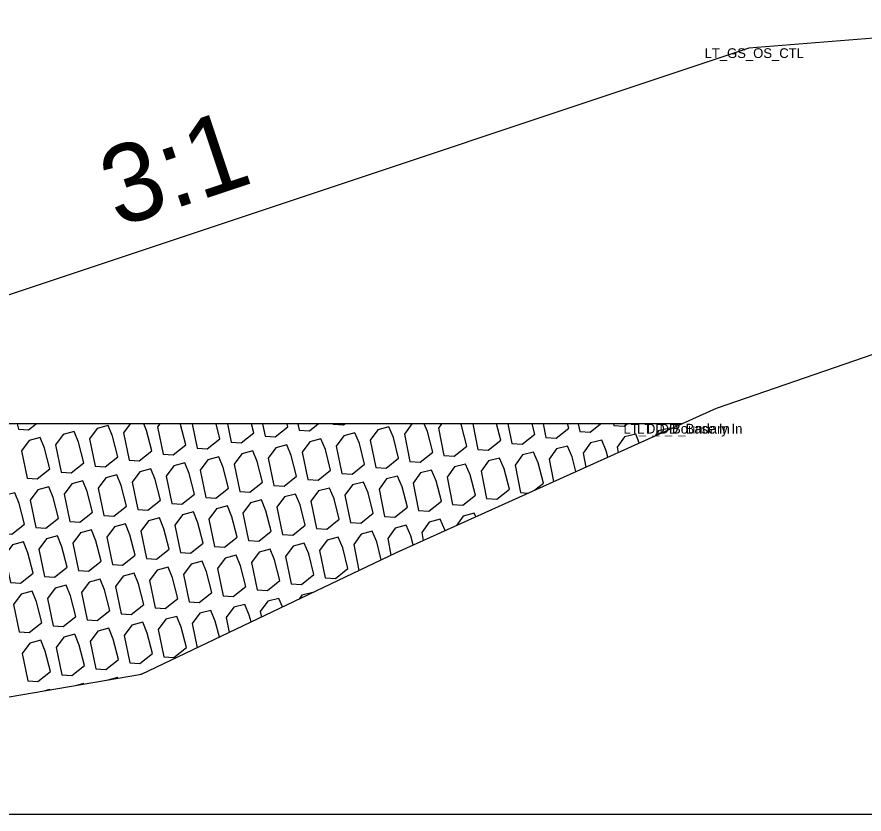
# Model space of a CAD drawing. Extents: x -26 to 203, y -10 to 20020.
# Drawn here: x 72.5 to 81.18, y 17500 to 17508.17 of the extents above; entities that cross this region are included whole.
import ezdxf

# ---------------------------------------------------------------- set-up
doc = ezdxf.new("R2010")
doc.units = 0
for name, color, linetype in [('Default', 7, 'Continuous'), ('Exist Cross Section Cell', 7, 'Continuous'), ('Exist XS Ground Line', 7, 'Continuous'), ('Old_Level_1', 7, 'Continuous'), ('Prop CMT Rip Rap Class II', 7, 'Continuous'), ('Prop CMT Slope Grass', 7, 'Continuous'), ('Prop XS Side Slope Text', 7, 'Continuous')]:
    doc.layers.add(name, color=color, linetype=linetype)

msp = doc.modelspace()

# ---------------------------------------------------------------- linework, layer by layer
at = {"layer": 'Exist Cross Section Cell'}
msp.add_line((0, 17500), (100, 17500), dxfattribs=at)
at = {"layer": 'Exist XS Ground Line'}
for p, q in [((79.6681, 17504.162), (84.6813, 17505.888)), ((76.389, 17502.6818), (79.6681, 17504.162)), ((73.7751, 17501.4325), (76.389, 17502.6818)), ((68.75, 17500.5802), (73.7751, 17501.4325))]:
    msp.add_line(p, q, dxfattribs=at)
at = {"layer": 'Old_Level_1'}
for p, q in [((72.5015, 17504), (72.5121, 17503.9468)), ((74.2943, 17504), (74.344, 17503.7501)), ((74.6551, 17504), (74.6926, 17503.8116)), ((75.0159, 17504), (75.0412, 17503.873)), ((75.3767, 17504), (75.3898, 17503.9345)), ((75.7375, 17504), (75.7383, 17503.996)), ((77.1695, 17504), (77.2216, 17503.7378)), ((77.5303, 17504), (77.5702, 17503.7992)), ((77.8911, 17504), (77.9188, 17503.8607)), ((78.2519, 17504), (78.2674, 17503.9222)), ((78.6128, 17504), (78.616, 17503.9836)), ((77.6591, 17503.2952), (77.7355, 17503.2896))]:
    msp.add_line(p, q, dxfattribs=at)
for points in [[(72.5121, 17503.9468), (72.6174, 17503.9392), (72.6937, 17504)], [(73.6584, 17504), (73.5912, 17503.9072), (73.6468, 17503.6272)], [(73.6468, 17503.6272), (73.752, 17503.6195), (73.8816, 17503.7227), (73.8271, 17503.9333), (73.7997, 17504)], [(73.9625, 17504), (73.9398, 17503.9686), (73.9954, 17503.6886)], [(73.9954, 17503.6886), (74.1006, 17503.681), (74.2302, 17503.7842), (74.1757, 17503.9948), (74.1736, 17504)], [(74.344, 17503.7501), (74.4492, 17503.7425), (74.5788, 17503.8457), (74.5389, 17504)], [(74.6926, 17503.8116), (74.7978, 17503.8039), (74.9274, 17503.9071), (74.9034, 17504)], [(75.0412, 17503.873), (75.1464, 17503.8654), (75.276, 17503.9686), (75.2678, 17504)], [(75.3898, 17503.9345), (75.495, 17503.9269), (75.5868, 17504)], [(75.7383, 17503.996), (75.8436, 17503.9883), (75.8583, 17504)], [(76.545, 17504), (76.4688, 17503.8948), (76.5244, 17503.6148)], [(76.5244, 17503.6148), (76.6297, 17503.6072), (76.7592, 17503.7104), (76.7048, 17503.921), (76.6723, 17504)], [(76.849, 17504), (76.8174, 17503.9563), (76.873, 17503.6763)], [(76.873, 17503.6763), (76.9783, 17503.6687), (77.1078, 17503.7719), (77.0534, 17503.9825), (77.0462, 17504)], [(77.2216, 17503.7378), (77.3269, 17503.7301), (77.4564, 17503.8333), (77.4133, 17504)], [(77.5702, 17503.7992), (77.6755, 17503.7916), (77.805, 17503.8948), (77.7778, 17504)], [(77.9188, 17503.8607), (78.0241, 17503.8531), (78.1536, 17503.9563), (78.1423, 17504)], [(78.2674, 17503.9222), (78.3727, 17503.9145), (78.4799, 17504)], [(78.616, 17503.9836), (78.7213, 17503.976), (78.7514, 17504)], [(79.1926, 17503.9474), (79.1887, 17503.9569), (79.0749, 17503.9275), (79.0392, 17503.8781)], [(78.5535, 17503.6589), (78.5366, 17503.7243), (78.4915, 17503.8339), (78.3777, 17503.8045), (78.3007, 17503.6981), (78.3286, 17503.5574)], [(78.8773, 17503.805), (78.8401, 17503.8954), (78.7263, 17503.866), (78.6493, 17503.7596), (78.6597, 17503.7068)], [(78.2271, 17503.5116), (78.188, 17503.6628), (78.1429, 17503.7725), (78.0291, 17503.7431), (77.9521, 17503.6366), (77.9975, 17503.4079)], [(77.8081, 17503.3224), (77.8939, 17503.3907), (77.8394, 17503.6013), (77.7943, 17503.711), (77.6805, 17503.6816), (77.6035, 17503.5752), (77.6591, 17503.2952)], [(73.0385, 17503.0002), (73.1437, 17502.9925), (73.2733, 17503.0957), (73.2188, 17503.3063), (73.1737, 17503.416), (73.0599, 17503.3866), (72.9828, 17503.2802), (73.0385, 17503.0002)], [(73.3871, 17503.0616), (73.4923, 17503.054), (73.6219, 17503.1572), (73.5674, 17503.3678), (73.5223, 17503.4775), (73.4085, 17503.4481), (73.3314, 17503.3416), (73.3871, 17503.0616)], [(72.6899, 17502.9387), (72.7951, 17502.9311), (72.9247, 17503.0343), (72.8702, 17503.2449), (72.8251, 17503.3545), (72.7113, 17503.3251), (72.6342, 17503.2187), (72.6899, 17502.9387)], [(75.2189, 17502.8649), (75.3242, 17502.8573), (75.4537, 17502.9605), (75.3993, 17503.1711), (75.3541, 17503.2807), (75.2404, 17503.2513), (75.1633, 17503.1449), (75.2189, 17502.8649)], [(74.5217, 17502.742), (74.627, 17502.7343), (74.7565, 17502.8375), (74.7021, 17503.0481), (74.6569, 17503.1578), (74.5432, 17503.1284), (74.4661, 17503.022), (74.5217, 17502.742)], [(74.8703, 17502.8034), (74.9756, 17502.7958), (75.1051, 17502.899), (75.0507, 17503.1096), (75.0055, 17503.2193), (74.8918, 17503.1899), (74.8147, 17503.0834), (74.8703, 17502.8034)], [(74.1731, 17502.6805), (74.2784, 17502.6729), (74.4079, 17502.7761), (74.3535, 17502.9866), (74.3083, 17503.0963), (74.1946, 17503.0669), (74.1175, 17502.9605), (74.1731, 17502.6805)], [(77.2007, 17503.0482), (77.186, 17503.084), (77.0722, 17503.0546), (77.003, 17502.959)], [(76.8844, 17502.9055), (76.8825, 17502.9128), (76.8374, 17503.0225), (76.7236, 17502.9931), (76.6466, 17502.8867), (76.6627, 17502.8054)], [(76.2326, 17502.6071), (76.1853, 17502.7899), (76.1402, 17502.8996), (76.0264, 17502.8702), (75.9494, 17502.7638), (76.0024, 17502.497)], [(76.5581, 17502.7581), (76.5339, 17502.8514), (76.4888, 17502.9611), (76.375, 17502.9317), (76.298, 17502.8252), (76.3319, 17502.6545)], [(75.6564, 17502.4223), (75.7617, 17502.4147), (75.8912, 17502.5179), (75.8368, 17502.7284), (75.7916, 17502.8381), (75.6778, 17502.8087), (75.6008, 17502.7023), (75.6564, 17502.4223)], [(75.532, 17502.2722), (75.5319, 17502.2726), (75.4181, 17502.2432), (75.39, 17502.2044)], [(75.2196, 17502.1229), (75.1833, 17502.2111), (75.0695, 17502.1817), (74.9925, 17502.0753), (75.0035, 17502.0196)], [(74.8981, 17501.9693), (74.8798, 17502.04), (74.8347, 17502.1497), (74.7209, 17502.1203), (74.6439, 17502.0138), (74.674, 17501.8621)], [(74.0023, 17501.6109), (74.1076, 17501.6033), (74.2371, 17501.7065), (74.1826, 17501.917), (74.1375, 17502.0267), (74.0237, 17501.9973), (73.9467, 17501.8909), (74.0023, 17501.6109)], [(74.5737, 17501.8142), (74.5312, 17501.9785), (74.4861, 17502.0882), (74.3723, 17502.0588), (74.2953, 17501.9524), (74.3445, 17501.7046)], [(72.6079, 17501.365), (72.7132, 17501.3574), (72.8427, 17501.4606), (72.7883, 17501.6712), (72.7431, 17501.7809), (72.6294, 17501.7515), (72.5523, 17501.645), (72.6079, 17501.365)], [(73.7849, 17501.4372), (73.764, 17501.4318), (73.7631, 17501.4305)], [(73.1831, 17501.3321), (73.1806, 17501.3383), (73.1067, 17501.3192)], [(73.5326, 17501.3914), (73.5292, 17501.3997), (73.4289, 17501.3738)], [(72.8336, 17501.2728), (72.832, 17501.2768), (72.7844, 17501.2645)]]:
    msp.add_lwpolyline(points, dxfattribs=at)
for points in [[(72.9496, 17503.5042), (73.0548, 17503.4966), (73.1844, 17503.5998), (73.1299, 17503.8104), (73.0848, 17503.9201), (72.971, 17503.8907), (72.894, 17503.7842)], [(73.2982, 17503.5657), (73.4034, 17503.5581), (73.533, 17503.6613), (73.4785, 17503.8719), (73.4334, 17503.9815), (73.3196, 17503.9521), (73.2426, 17503.8457)], [(76.1758, 17503.5534), (76.2811, 17503.5457), (76.4106, 17503.6489), (76.3562, 17503.8595), (76.311, 17503.9692), (76.1973, 17503.9398), (76.1202, 17503.8334)], [(72.601, 17503.4428), (72.7062, 17503.4351), (72.8358, 17503.5383), (72.7813, 17503.7489), (72.7362, 17503.8586), (72.6224, 17503.8292), (72.5454, 17503.7228)], [(75.4786, 17503.4304), (75.5839, 17503.4228), (75.7134, 17503.526), (75.659, 17503.7366), (75.6138, 17503.8463), (75.5001, 17503.8169), (75.423, 17503.7104)], [(75.8272, 17503.4919), (75.9325, 17503.4843), (76.062, 17503.5875), (76.0076, 17503.7981), (75.9624, 17503.9077), (75.8487, 17503.8783), (75.7716, 17503.7719)], [(75.13, 17503.369), (75.2353, 17503.3613), (75.3648, 17503.4645), (75.3104, 17503.6751), (75.2652, 17503.7848), (75.1515, 17503.7554), (75.0744, 17503.649)], [(74.4328, 17503.246), (74.5381, 17503.2384), (74.6676, 17503.3416), (74.6132, 17503.5522), (74.5681, 17503.6619), (74.4543, 17503.6325), (74.3772, 17503.526)], [(74.7814, 17503.3075), (74.8867, 17503.2999), (75.0162, 17503.4031), (74.9618, 17503.6137), (74.9167, 17503.7233), (74.8029, 17503.6939), (74.7258, 17503.5875)], [(74.0842, 17503.1846), (74.1895, 17503.1769), (74.319, 17503.2801), (74.2646, 17503.4907), (74.2195, 17503.6004), (74.1057, 17503.571), (74.0286, 17503.4646)], [(76.9619, 17503.1722), (77.0672, 17503.1646), (77.1967, 17503.2678), (77.1423, 17503.4784), (77.0971, 17503.5881), (76.9834, 17503.5587), (76.9063, 17503.4522)], [(77.3105, 17503.2337), (77.4158, 17503.2261), (77.5453, 17503.3293), (77.4909, 17503.5399), (77.4457, 17503.6495), (77.3319, 17503.6201), (77.2549, 17503.5137)], [(73.7356, 17503.1231), (73.8409, 17503.1155), (73.9705, 17503.2187), (73.916, 17503.4293), (73.8709, 17503.5389), (73.7571, 17503.5095), (73.68, 17503.4031)], [(76.6133, 17503.1108), (76.7186, 17503.1031), (76.8481, 17503.2063), (76.7937, 17503.4169), (76.7485, 17503.5266), (76.6348, 17503.4972), (76.5577, 17503.3908)], [(75.9161, 17502.9878), (76.0214, 17502.9802), (76.1509, 17503.0834), (76.0965, 17503.294), (76.0513, 17503.4037), (75.9376, 17503.3743), (75.8605, 17503.2678)], [(76.2647, 17503.0493), (76.37, 17503.0417), (76.4995, 17503.1449), (76.4451, 17503.3555), (76.3999, 17503.4651), (76.2862, 17503.4357), (76.2091, 17503.3293)], [(75.5675, 17502.9264), (75.6728, 17502.9187), (75.8023, 17503.0219), (75.7479, 17503.2325), (75.7027, 17503.3422), (75.589, 17503.3128), (75.5119, 17503.2064)], [(72.3413, 17502.8772), (72.4465, 17502.8696), (72.5761, 17502.9728), (72.5216, 17503.1834), (72.4765, 17503.2931), (72.3627, 17503.2637), (72.2857, 17503.1572)], [(73.4759, 17502.5576), (73.5812, 17502.5499), (73.7107, 17502.6531), (73.6563, 17502.8637), (73.6111, 17502.9734), (73.4974, 17502.944), (73.4203, 17502.8376)], [(73.8245, 17502.619), (73.9298, 17502.6114), (74.0593, 17502.7146), (74.0049, 17502.9252), (73.9597, 17503.0349), (73.846, 17503.0055), (73.7689, 17502.899)], [(73.1273, 17502.4961), (73.2326, 17502.4885), (73.3621, 17502.5917), (73.3077, 17502.8022), (73.2625, 17502.9119), (73.1488, 17502.8825), (73.0717, 17502.7761)], [(72.7787, 17502.4346), (72.884, 17502.427), (73.0135, 17502.5302), (72.9591, 17502.7408), (72.914, 17502.8505), (72.8002, 17502.8211), (72.7231, 17502.7146)], [(72.4301, 17502.3732), (72.5354, 17502.3655), (72.6649, 17502.4687), (72.6105, 17502.6793), (72.5654, 17502.789), (72.4516, 17502.7596), (72.3745, 17502.6532)], [(74.9592, 17502.2994), (75.0645, 17502.2917), (75.194, 17502.3949), (75.1396, 17502.6055), (75.0944, 17502.7152), (74.9807, 17502.6858), (74.9036, 17502.5794)], [(75.3078, 17502.3608), (75.4131, 17502.3532), (75.5426, 17502.4564), (75.4882, 17502.667), (75.443, 17502.7767), (75.3292, 17502.7473), (75.2522, 17502.6408)], [(74.6106, 17502.2379), (74.7159, 17502.2303), (74.8454, 17502.3335), (74.791, 17502.544), (74.7458, 17502.6537), (74.6321, 17502.6243), (74.555, 17502.5179)], [(73.9134, 17502.115), (74.0187, 17502.1073), (74.1482, 17502.2105), (74.0938, 17502.4211), (74.0486, 17502.5308), (73.9349, 17502.5014), (73.8578, 17502.395)], [(74.262, 17502.1764), (74.3673, 17502.1688), (74.4968, 17502.272), (74.4424, 17502.4826), (74.3972, 17502.5923), (74.2835, 17502.5629), (74.2064, 17502.4564)], [(73.5648, 17502.0535), (73.6701, 17502.0459), (73.7996, 17502.1491), (73.7452, 17502.3596), (73.7, 17502.4693), (73.5863, 17502.4399), (73.5092, 17502.3335)], [(73.2162, 17501.992), (73.3215, 17501.9844), (73.451, 17502.0876), (73.3966, 17502.2982), (73.3514, 17502.4079), (73.2377, 17502.3785), (73.1606, 17502.272)], [(72.519, 17501.8691), (72.6243, 17501.8615), (72.7538, 17501.9647), (72.6994, 17502.1752), (72.6542, 17502.2849), (72.5405, 17502.2555), (72.4634, 17502.1491)], [(72.8676, 17501.9306), (72.9729, 17501.9229), (73.1024, 17502.0261), (73.048, 17502.2367), (73.0028, 17502.3464), (72.8891, 17502.317), (72.812, 17502.2106)], [(73.6537, 17501.5494), (73.759, 17501.5418), (73.8885, 17501.645), (73.8341, 17501.8556), (73.7889, 17501.9653), (73.6751, 17501.9359), (73.5981, 17501.8294)], [(72.9565, 17501.4265), (73.0618, 17501.4189), (73.1913, 17501.5221), (73.1369, 17501.7326), (73.0917, 17501.8423), (72.978, 17501.8129), (72.9009, 17501.7065)], [(73.3051, 17501.488), (73.4104, 17501.4803), (73.5399, 17501.5835), (73.4855, 17501.7941), (73.4403, 17501.9038), (73.3266, 17501.8744), (73.2495, 17501.768)]]:
    msp.add_lwpolyline(points, close=True, dxfattribs=at)
at = {"layer": 'Prop CMT Rip Rap Class II'}
for points in [[(79.3093, 17504), (66.4497, 17504), (62.4908, 17501.3606)], [(79.3093, 17504), (79.3093, 17504)]]:
    msp.add_lwpolyline(points, dxfattribs=at)
at = {"layer": 'Prop CMT Slope Grass'}
for points in [[(84.0133, 17508.1708), (80, 17507.8497)], [(80, 17507.8497), (68.4497, 17504)]]:
    msp.add_lwpolyline(points, dxfattribs=at)

# ---------------------------------------------------------------- texts
at = {"layer": 'Default'}
for s, p in [('LT_GS_OS_CTL', (79.5464, 17507.7497)), ('LT_DD_Boundary In', (78.7151, 17503.9)), ('LT_DD_Base In', (78.8538, 17503.9))]:
    msp.add_text(s, height=0.1, dxfattribs=at).set_placement(p)
at = {"layer": 'Prop XS Side Slope Text'}
msp.add_text('3:1', height=0.8, rotation=18.43323, dxfattribs=at).set_placement((73.5285, 17506.009))

doc.saveas('drawing.dxf')
